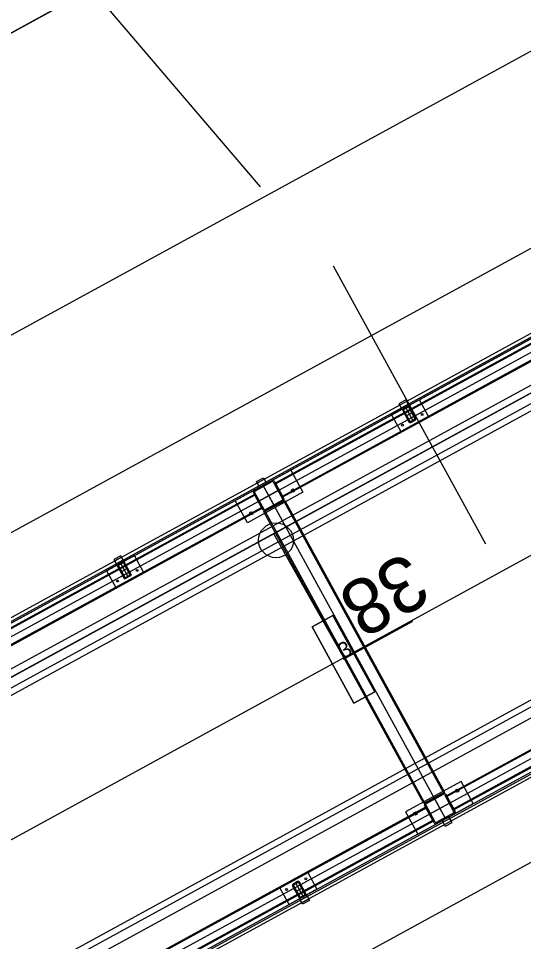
# Model space of a CAD drawing. Extents: x -783978 to -783565, y -1064821 to -1064596.
# Drawn here: x -783762.94 to -783759.75, y -1064681.64 to -1064675.81 of the extents above; entities that cross this region are included whole.
import ezdxf

# ---------------------------------------------------------------- set-up
doc = ezdxf.new("R2010")
doc.units = 0
for name, color, linetype in [('_PS_SO_číslo', 7, 'Continuous'), ('Default', 7, 'Continuous'), ('PS 01_01_10', 7, 'Continuous'), ('PS 01_02_501', 7, 'Continuous'), ('PS 01_02_502', 7, 'Continuous'), ('SO 01_11_01', 7, 'Continuous'), ('SO 01_20_01', 7, 'Continuous'), ('SO 01_50_01', 7, 'Continuous'), ('SO 01_74_01', 7, 'Continuous'), ('SO 01_86_03', 7, 'Continuous'), ('SO 01_86_04', 7, 'Continuous')]:
    doc.layers.add(name, color=color, linetype=linetype)

# ---------------------------------------------------------------- blocks, each defined once
blk = doc.blocks.new('POINT_DISPLAY')
at = {"layer": 'Default'}
blk.add_line((0, 0), (0, 0), dxfattribs=at)

msp = doc.modelspace()

# ---------------------------------------------------------------- linework, layer by layer
at = {"layer": '_PS_SO_číslo'}
msp.add_line((-783761.4118, -1064676.8772), (-783778.1513, -1064657.2448), dxfattribs=at)
at = {"layer": 'PS 01_01_10'}
msp.add_lwpolyline([(-783718.9415, -1064658.9356), (-783725.9639, -1064662.6889), (-783732.3538, -1064665.9121), (-783735.2095, -1064660.6967), (-783789.362, -1064690.3481), (-783783.8255, -1064700.4409), (-783871.4362, -1064748.4249), (-783875.857, -1064749.8347)], dxfattribs=at)
at = {"layer": 'PS 01_02_501'}
msp.add_lwpolyline([(-783952.3105, -1064789.972), (-783925.027, -1064771.233), (-783922.857, -1064767.935), (-783921.1315, -1064767.225), (-783922.344, -1064769.056), (-783920.816, -1064771.043), (-783917.67, -1064770.417), (-783911.05, -1064766.471), (-783887.429, -1064753.525), (-783871.4362, -1064748.4249), (-783783.8277, -1064700.4386), (-783789.362, -1064690.3481), (-783735.2263, -1064660.7067), (-783727.1901, -1064659.072), (-783724.297, -1064658.4835), (-783715.521, -1064653.988), (-783697.391, -1064644.148), (-783676.268, -1064633.506), (-783655.138, -1064621.894)], dxfattribs=at)
at = {"layer": 'PS 01_02_502'}
msp.add_lwpolyline([(-783952.3105, -1064789.972), (-783925.027, -1064771.233), (-783922.857, -1064767.935), (-783921.1315, -1064767.225), (-783922.344, -1064769.056), (-783920.816, -1064771.043), (-783917.67, -1064770.417), (-783911.05, -1064766.471), (-783887.429, -1064753.525), (-783871.4362, -1064748.4249), (-783783.8277, -1064700.4386), (-783789.362, -1064690.3481), (-783735.2263, -1064660.7067), (-783727.1901, -1064659.072), (-783724.297, -1064658.4835), (-783715.521, -1064653.988), (-783697.391, -1064644.148), (-783676.268, -1064633.506), (-783655.138, -1064621.894)], dxfattribs=at)
at = {"layer": 'SO 01_11_01'}
msp.add_line((-783772.8819, -1064683.2217), (-783730.898, -1064660.279), dxfattribs=at)
at = {"layer": 'SO 01_20_01'}
for p, q in [((-783735.0054, -1064663.7532), (-783787.4671, -1064692.4555)), ((-783735.2041, -1064664.4318), (-783786.7885, -1064692.6541)), ((-783786.6445, -1064692.9173), (-783735.3233, -1064664.839)), ((-783738.0171, -1064666.3812), (-783786.4402, -1064692.874)), ((-783786.421, -1064692.9091), (-783737.9979, -1064666.4163)), ((-783737.8741, -1064667.2605), (-783785.3352, -1064693.2269)), ((-783785.6531, -1064694.3127), (-783737.23, -1064667.82)), ((-783737.0912, -1064667.858), (-783785.7805, -1064694.4964)), ((-783737.2108, -1064667.855), (-783785.6339, -1064694.3478)), ((-783785.6366, -1064694.7596), (-783736.9472, -1064668.1212)), ((-783746.2961, -1064673.8055), (-783785.8354, -1064695.4379))]:
    msp.add_line(p, q, dxfattribs=at)
at = {"layer": 'SO 01_50_01'}
for p, q in [((-783786.7885, -1064692.6541), (-783725.4827, -1064659.1131)), ((-783760.47, -1064678.255), (-783756.0835, -1064675.8552)), ((-783760.4699, -1064678.2551), (-783756.0835, -1064675.8552)), ((-783760.4699, -1064678.2551), (-783756.0835, -1064675.8552)), ((-783759.99, -1064679.1323), (-783760.9499, -1064677.3777)), ((-783764.8564, -1064680.6549), (-783760.47, -1064678.255)), ((-783764.8563, -1064680.655), (-783760.4699, -1064678.2551)), ((-783764.8563, -1064680.655), (-783760.4699, -1064678.2551))]:
    msp.add_line(p, q, dxfattribs=at)
at = {"layer": 'SO 01_74_01'}
for p, q in [((-783735.2185, -1064664.4055), (-783786.6099, -1064692.5222)), ((-783786.6003, -1064692.5398), (-783735.2089, -1064664.423)), ((-783785.4388, -1064694.6628), (-783745.8293, -1064672.9921)), ((-783745.8197, -1064673.0096), (-783785.4292, -1064694.6803)), ((-783758.7516, -1064677.3434), (-783761.3177, -1064678.7473)), ((-783758.7486, -1064677.3489), (-783761.3147, -1064678.7528)), ((-783761.2727, -1064678.8295), (-783758.7067, -1064677.4256)), ((-783761.2697, -1064678.835), (-783758.7036, -1064677.4311)), ((-783760.4935, -1064678.2223), (-783760.5374, -1064678.2463)), ((-783760.4743, -1064678.2574), (-783760.4935, -1064678.2223)), ((-783760.5374, -1064678.2463), (-783760.5182, -1064678.2814)), ((-783760.4887, -1064678.2311), (-783760.5326, -1064678.2551)), ((-783760.5326, -1064678.2551), (-783760.523, -1064678.2726)), ((-783760.523, -1064678.2726), (-783760.4791, -1064678.2486)), ((-783760.5182, -1064678.2814), (-783760.4743, -1064678.2574)), ((-783760.4791, -1064678.2486), (-783760.4887, -1064678.2311)), ((-783761.4366, -1064678.7383), (-783761.3928, -1064678.7143)), ((-783761.4174, -1064678.7734), (-783761.4366, -1064678.7383)), ((-783761.3928, -1064678.7143), (-783761.3736, -1064678.7494)), ((-783761.3177, -1064678.7473), (-783761.2697, -1064678.835)), ((-783761.3736, -1064678.7494), (-783761.4174, -1064678.7734)), ((-783761.3147, -1064678.7528), (-783761.2727, -1064678.8295)), ((-783761.4493, -1064678.8193), (-783764.0153, -1064680.2232)), ((-783761.4463, -1064678.8248), (-783764.0123, -1064680.2288)), ((-783761.4013, -1064678.907), (-783761.4493, -1064678.8193)), ((-783761.4043, -1064678.9015), (-783761.4463, -1064678.8248)), ((-783761.3893, -1064678.929), (-783761.2577, -1064678.857)), ((-783761.3823, -1064678.9251), (-783761.2647, -1064678.8608)), ((-783761.2647, -1064678.8608), (-783760.2568, -1064680.7031)), ((-783761.2577, -1064678.857), (-783760.2498, -1064680.6993)), ((-783763.9704, -1064680.3054), (-783761.4043, -1064678.9015)), ((-783763.9673, -1064680.311), (-783761.4013, -1064678.907)), ((-783760.3813, -1064680.7713), (-783761.3893, -1064678.929)), ((-783760.3743, -1064680.7674), (-783761.3823, -1064678.9251)), ((-783762.292, -1064679.2063), (-783762.3358, -1064679.2303)), ((-783762.2872, -1064679.215), (-783762.331, -1064679.239)), ((-783762.2728, -1064679.2414), (-783762.292, -1064679.2063)), ((-783762.2776, -1064679.2326), (-783762.2872, -1064679.215)), ((-783762.3358, -1064679.2303), (-783762.3166, -1064679.2654)), ((-783762.331, -1064679.239), (-783762.3214, -1064679.2566)), ((-783762.3214, -1064679.2566), (-783762.2776, -1064679.2326)), ((-783762.3166, -1064679.2654), (-783762.2728, -1064679.2414)), ((-783757.6717, -1064679.3173), (-783760.2378, -1064680.7212)), ((-783757.6687, -1064679.3228), (-783760.2347, -1064680.7267)), ((-783760.1928, -1064680.8034), (-783757.6267, -1064679.3995)), ((-783760.1898, -1064680.8089), (-783757.6237, -1064679.405)), ((-783760.2498, -1064680.6993), (-783760.3813, -1064680.7713)), ((-783760.2568, -1064680.7031), (-783760.3743, -1064680.7674)), ((-783760.2378, -1064680.7212), (-783760.1898, -1064680.8089)), ((-783760.2347, -1064680.7267), (-783760.1928, -1064680.8034)), ((-783760.3694, -1064680.7932), (-783762.9354, -1064682.1971)), ((-783760.3663, -1064680.7987), (-783762.9324, -1064682.2026)), ((-783760.3214, -1064680.8809), (-783760.3694, -1064680.7932)), ((-783760.3244, -1064680.8754), (-783760.3663, -1064680.7987)), ((-783762.8904, -1064682.2793), (-783760.3244, -1064680.8754)), ((-783762.8874, -1064682.2848), (-783760.3214, -1064680.8809)), ((-783760.2216, -1064680.8549), (-783760.2655, -1064680.8789)), ((-783760.2655, -1064680.8789), (-783760.2463, -1064680.914)), ((-783760.2463, -1064680.914), (-783760.2024, -1064680.89)), ((-783760.2024, -1064680.89), (-783760.2216, -1064680.8549)), ((-783761.1647, -1064681.3708), (-783761.1208, -1064681.3468)), ((-783761.1455, -1064681.4059), (-783761.1647, -1064681.3708)), ((-783761.1599, -1064681.3796), (-783761.116, -1064681.3556)), ((-783761.1208, -1064681.3468), (-783761.1016, -1064681.3819)), ((-783761.116, -1064681.3556), (-783761.1064, -1064681.3732)), ((-783761.1503, -1064681.3972), (-783761.1599, -1064681.3796)), ((-783761.1064, -1064681.3732), (-783761.1503, -1064681.3972)), ((-783761.1016, -1064681.3819), (-783761.1455, -1064681.4059))]:
    msp.add_line(p, q, dxfattribs=at)
for points in [[(-783735.1681, -1064664.4976), (-783787.4762, -1064693.1159)], [(-783734.0882, -1064666.4715), (-783786.3963, -1064695.0898)], [(-783760.4826, -1064678.2619), (-783760.5099, -1064678.2769)], [(-783760.4796, -1064678.2675), (-783760.5069, -1064678.2824)], [(-783760.4963, -1064678.2694), (-783760.4483, -1064678.3571)], [(-783760.4364, -1064678.3399), (-783760.4753, -1064678.2687)], [(-783760.4309, -1064678.3369), (-783760.4698, -1064678.2657)], [(-783760.5137, -1064678.2897), (-783760.4747, -1064678.3609)], [(-783760.5081, -1064678.2867), (-783760.4692, -1064678.3578)], [(-783760.4503, -1064678.3013), (-783760.4942, -1064678.3253)], [(-783760.4649, -1064678.3591), (-783760.4377, -1064678.3442)], [(-783760.4619, -1064678.3646), (-783760.4346, -1064678.3497)], [(-783761.4508, -1064678.7916), (-783761.3402, -1064678.7311)], [(-783761.4469, -1064678.7986), (-783761.3364, -1064678.7382)], [(-783761.3309, -1064678.7398), (-783761.2705, -1064678.8503)], [(-783761.3239, -1064678.7359), (-783761.2635, -1064678.8465)], [(-783761.388, -1064678.9146), (-783761.4485, -1064678.8041)], [(-783761.2937, -1064678.7912), (-783761.4253, -1064678.8632)], [(-783761.3955, -1064678.7614), (-783760.2436, -1064680.8669)], [(-783761.3955, -1064678.7614), (-783761.3235, -1064678.893)], [(-783761.395, -1064678.9184), (-783761.4555, -1064678.8079)], [(-783761.2721, -1064678.8557), (-783761.3826, -1064678.9162)], [(-783761.2682, -1064678.8627), (-783761.3788, -1064678.9232)], [(-783762.2811, -1064679.2459), (-783762.3083, -1064679.2608)], [(-783762.3066, -1064679.2706), (-783762.2676, -1064679.3418)], [(-783762.278, -1064679.2514), (-783762.3053, -1064679.2663)], [(-783762.2947, -1064679.2534), (-783762.2467, -1064679.3411)], [(-783762.2348, -1064679.3238), (-783762.2738, -1064679.2527)], [(-783762.2293, -1064679.3208), (-783762.2682, -1064679.2496)], [(-783762.3121, -1064679.2736), (-783762.2732, -1064679.3448)], [(-783762.2488, -1064679.2852), (-783762.2926, -1064679.3092)], [(-783762.2634, -1064679.343), (-783762.2361, -1064679.3281)], [(-783762.2603, -1064679.3485), (-783762.2331, -1064679.3336)], [(-783760.3708, -1064680.7655), (-783760.2603, -1064680.705)], [(-783760.367, -1064680.7725), (-783760.2564, -1064680.7121)], [(-783760.251, -1064680.7136), (-783760.1905, -1064680.8242)], [(-783760.244, -1064680.7098), (-783760.1835, -1064680.8203)], [(-783760.3151, -1064680.8923), (-783760.3756, -1064680.7818)], [(-783760.3081, -1064680.8885), (-783760.3686, -1064680.778)], [(-783760.2138, -1064680.7651), (-783760.3454, -1064680.8371)], [(-783760.3156, -1064680.7353), (-783760.2436, -1064680.8669)], [(-783760.1921, -1064680.8296), (-783760.3027, -1064680.8901)], [(-783760.1883, -1064680.8366), (-783760.2988, -1064680.8971)], [(-783761.2082, -1064681.2914), (-783761.1692, -1064681.3625)], [(-783761.1771, -1064681.2636), (-783761.2044, -1064681.2786)], [(-783761.2026, -1064681.2884), (-783761.1637, -1064681.3595)], [(-783761.1741, -1064681.2692), (-783761.2014, -1064681.2841)], [(-783761.1908, -1064681.2711), (-783761.1428, -1064681.3588)], [(-783761.1448, -1064681.303), (-783761.1887, -1064681.327)], [(-783761.1309, -1064681.3416), (-783761.1698, -1064681.2704)], [(-783761.1254, -1064681.3385), (-783761.1643, -1064681.2674)], [(-783761.1594, -1064681.3608), (-783761.1322, -1064681.3458)], [(-783761.1564, -1064681.3663), (-783761.1291, -1064681.3514)]]:
    msp.add_lwpolyline(points, dxfattribs=at)
for points in [[(-783760.4085, -1064678.2214), (-783760.584, -1064678.3174), (-783760.5264, -1064678.4227), (-783760.3509, -1064678.3267)], [(-783761.1432, -1064678.8058), (-783761.4941, -1064678.9977), (-783761.5709, -1064678.8574), (-783761.22, -1064678.6654)], [(-783762.207, -1064679.2054), (-783762.3824, -1064679.3014), (-783762.3248, -1064679.4066), (-783762.1494, -1064679.3106)], [(-783762.2728, -1064679.2414), (-783762.3166, -1064679.2654), (-783762.2686, -1064679.3531), (-783762.2248, -1064679.3291)], [(-783760.1449, -1064680.6305), (-783760.4958, -1064680.8225), (-783760.419, -1064680.9629), (-783760.0681, -1064680.7709)], [(-783761.055, -1064681.3108), (-783761.2305, -1064681.4068), (-783761.2881, -1064681.3016), (-783761.1126, -1064681.2056)]]:
    msp.add_lwpolyline(points, close=True, dxfattribs=at)
for centre, radius in [((-783760.3917, -1064678.3148), 0.006), ((-783760.5145, -1064678.382), 0.006), ((-783761.2063, -1064678.7947), 0.01), ((-783761.4695, -1064678.9387), 0.01), ((-783762.1901, -1064679.2987), 0.006), ((-783762.3129, -1064679.3659), 0.006), ((-783760.1696, -1064680.6896), 0.01), ((-783760.4327, -1064680.8336), 0.01), ((-783761.1246, -1064681.2463), 0.006), ((-783761.2474, -1064681.3135), 0.006)]:
    msp.add_circle(centre, radius, dxfattribs=at)
for centre, radius, start, end in [((-783760.5054, -1064678.2852), 0.00945, 118.68349, 208.68349), ((-783760.5054, -1064678.2852), 0.00315, 118.68349, 208.68349), ((-783760.4781, -1064678.2702), 0.00945, 28.68349, 118.68349), ((-783760.4781, -1064678.2702), 0.00315, 28.68349, 118.68349), ((-783760.4392, -1064678.3414), 0.00315, 298.68349, 28.68349), ((-783760.4392, -1064678.3414), 0.00945, 298.68349, 28.68349), ((-783760.4665, -1064678.3563), 0.00945, 208.68349, 298.68349), ((-783760.4665, -1064678.3563), 0.00315, 208.68349, 298.68349), ((-783761.3345, -1064678.7417), 0.012, 28.68349, 118.68349), ((-783761.3345, -1064678.7417), 0.004, 28.68349, 118.68349), ((-783761.445, -1064678.8021), 0.012, 118.68349, 208.68349), ((-783761.445, -1064678.8021), 0.004, 118.68349, 208.68349), ((-783761.274, -1064678.8522), 0.004, 298.68349, 28.68349), ((-783761.274, -1064678.8522), 0.012, 298.68349, 28.68349), ((-783761.3845, -1064678.9127), 0.012, 208.68349, 298.68349), ((-783761.3845, -1064678.9127), 0.004, 208.68349, 298.68349), ((-783762.3038, -1064679.2691), 0.00945, 118.68349, 208.68349), ((-783762.3038, -1064679.2691), 0.00315, 118.68349, 208.68349), ((-783762.2765, -1064679.2542), 0.00945, 28.68349, 118.68349), ((-783762.2765, -1064679.2542), 0.00315, 28.68349, 118.68349), ((-783762.2376, -1064679.3253), 0.00315, 298.68349, 28.68349), ((-783762.2376, -1064679.3253), 0.00945, 298.68349, 28.68349), ((-783762.2649, -1064679.3403), 0.00945, 208.68349, 298.68349), ((-783762.2649, -1064679.3403), 0.00315, 208.68349, 298.68349), ((-783760.2545, -1064680.7156), 0.012, 28.68349, 118.68349), ((-783760.2545, -1064680.7156), 0.004, 28.68349, 118.68349), ((-783760.3651, -1064680.776), 0.012, 118.68349, 208.68349), ((-783760.3651, -1064680.776), 0.004, 118.68349, 208.68349), ((-783760.194, -1064680.8261), 0.004, 298.68349, 28.68349), ((-783760.194, -1064680.8261), 0.012, 298.68349, 28.68349), ((-783760.3046, -1064680.8866), 0.012, 208.68349, 298.68349), ((-783760.3046, -1064680.8866), 0.004, 208.68349, 298.68349), ((-783761.1999, -1064681.2869), 0.00945, 118.68349, 208.68349), ((-783761.1999, -1064681.2869), 0.00315, 118.68349, 208.68349), ((-783761.1726, -1064681.2719), 0.00945, 28.68349, 118.68349), ((-783761.1726, -1064681.2719), 0.00315, 28.68349, 118.68349), ((-783761.161, -1064681.358), 0.00945, 208.68349, 298.68349), ((-783761.161, -1064681.358), 0.00315, 208.68349, 298.68349), ((-783761.1337, -1064681.3431), 0.00315, 298.68349, 28.68349), ((-783761.1337, -1064681.3431), 0.00945, 298.68349, 28.68349)]:
    msp.add_arc(centre, radius, start, end, dxfattribs=at)
at = {"layer": 'SO 01_86_03'}
for points in [[(-783722.5212, -1064661.7932), (-783724.8208, -1064663.0486), (-783735.2095, -1064660.6967), (-783787.333, -1064689.2371), (-783786.8168, -1064690.1799), (-783783.3595, -1064696.8031), (-783781.9388, -1064699.4088), (-783783.8277, -1064700.4386), (-783871.4362, -1064748.4249), (-783875.857, -1064749.8347), (-783877.5381, -1064747.3925), (-783875.857, -1064749.8347), (-783887.429, -1064753.525), (-783911.05, -1064766.471), (-783917.67, -1064770.417), (-783920.816, -1064771.043), (-783922.344, -1064769.056), (-783922.498, -1064767.051)], [(-783747.0305, -1064676.621), (-783747.6236, -1064677.108), (-783750.7299, -1064678.7824), (-783751.6662, -1064678.8522), (-783782.6812, -1064695.8307), (-783782.8877, -1064696.6917), (-783783.0615, -1064696.8198), (-783783.3595, -1064696.8031), (-783786.8168, -1064690.1799), (-783787.333, -1064689.2371), (-783735.2095, -1064660.6967), (-783724.8208, -1064663.0486), (-783722.5212, -1064661.7932)]]:
    msp.add_lwpolyline(points, dxfattribs=at)
at = {"layer": 'SO 01_86_04'}
for p, q in [((-783761.3282, -1064679.0665), (-783760.8725, -1064679.8732)), ((-783760.9542, -1064679.583), (-783761.0858, -1064679.655)), ((-783760.9542, -1064679.583), (-783761.0858, -1064679.655)), ((-783761.0858, -1064679.655), (-783760.9542, -1064679.583)), ((-783761.0858, -1064679.655), (-783760.9542, -1064679.583)), ((-783760.6902, -1064680.0655), (-783760.9542, -1064679.583)), ((-783760.6902, -1064680.0655), (-783760.9542, -1064679.583)), ((-783760.9542, -1064679.583), (-783760.6902, -1064680.0655)), ((-783760.9542, -1064679.583), (-783760.6902, -1064680.0655)), ((-783760.888, -1064679.8602), (-783760.4493, -1064679.6202)), ((-783761.0858, -1064679.655), (-783760.8218, -1064680.1375)), ((-783761.0858, -1064679.655), (-783760.8218, -1064680.1375)), ((-783760.8218, -1064680.1375), (-783761.0858, -1064679.655)), ((-783760.8218, -1064680.1375), (-783761.0858, -1064679.655)), ((-783760.8218, -1064680.1375), (-783760.6902, -1064680.0655)), ((-783760.8218, -1064680.1375), (-783760.6902, -1064680.0655)), ((-783760.6902, -1064680.0655), (-783760.8218, -1064680.1375)), ((-783760.6902, -1064680.0655), (-783760.8218, -1064680.1375))]:
    msp.add_line(p, q, dxfattribs=at)
for points in [[(-783738.3222, -1064666.4797), (-783740.5325, -1064667.689), (-783743.1715, -1064669.1328), (-783745.7538, -1064670.5456), (-783748.4385, -1064672.0145), (-783751.0413, -1064673.4385), (-783753.6847, -1064674.8847), (-783756.3281, -1064676.3309), (-783758.9715, -1064677.7772), (-783761.6149, -1064679.2234), (-783764.2583, -1064680.6696), (-783766.9018, -1064682.1159), (-783769.4633, -1064683.5173), (-783772.109, -1064684.9648), (-783774.7882, -1064686.4306), (-783778.1382, -1064688.2722), (-783783.8139, -1064691.3971), (-783785.747, -1064692.4898)], [(-783747.063, -1064670.9765), (-783746.9575, -1064671.1681), (-783786.6893, -1064692.8619), (-783786.185, -1064693.7636)]]:
    msp.add_lwpolyline(points, dxfattribs=at)
msp.add_circle((-783761.3132, -1064679.1089), 0.1097, dxfattribs=at)

# ---------------------------------------------------------------- block references
at = {"layer": 'SO 01_86_04', "xscale": 0.010000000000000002, "yscale": 0.009999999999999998, "rotation": 28.683491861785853}
for p in [(-783760.9542, -1064679.583), (-783760.9542, -1064679.583), (-783761.0858, -1064679.655), (-783761.0858, -1064679.655), (-783760.6902, -1064680.0655), (-783760.6902, -1064680.0655), (-783760.8218, -1064680.1375), (-783760.8218, -1064680.1375)]:
    msp.add_blockref('POINT_DISPLAY', p, dxfattribs=at)

# ---------------------------------------------------------------- texts
at = {"layer": 'SO 01_86_04'}
for s, height, rotation, p in [('38', 0.351, 209.46001, (-783760.487, -1064679.175)), ('3', 0.1, 28.68349, (-783760.888, -1064679.8602))]:
    msp.add_text(s, height=height, rotation=rotation, dxfattribs=at).set_placement(p)

doc.saveas('drawing.dxf')
